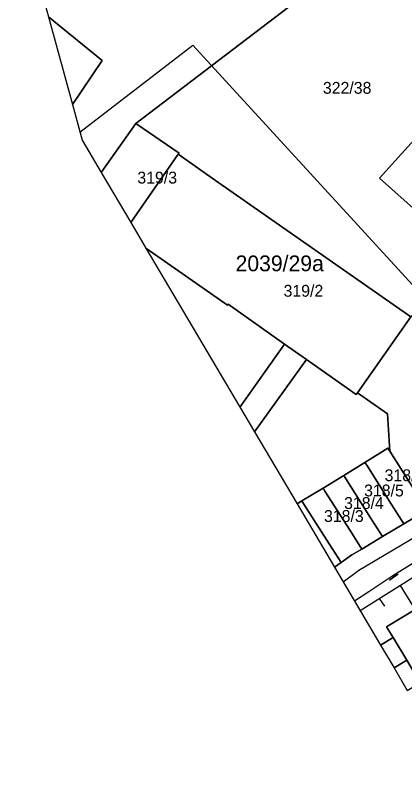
# Model space of a CAD drawing. Extents: x -571312 to -571060, y -1087128 to -1086933.
# Drawn here: x -571301.1 to -571251.9, y -1087104.3 to -1087007.2 of the extents above; entities that cross this region are included whole.
import ezdxf

# ---------------------------------------------------------------- set-up
doc = ezdxf.new("R2010")
doc.units = 0
for name, color, linetype in [('Adresní místo-text', 7, 'Continuous'), ('Armatura vodovodní', 7, 'Continuous'), ('Kanalizační přípojka', 7, 'Continuous'), ('Kanalizační stoka', 7, 'Continuous'), ('Parcela-polygon', 7, 'Continuous'), ('Parcela-text', 7, 'Continuous'), ('Vodovodní přípojka', 7, 'Continuous'), ('Vodovodní řad', 7, 'Continuous')]:
    doc.layers.add(name, color=color, linetype=linetype)

msp = doc.modelspace()

# ---------------------------------------------------------------- linework, layer by layer
at = {"layer": 'Armatura vodovodní'}
msp.add_lwpolyline([(-571252.784, -1087077.94), (-571253.789, -1087078.683), (-571253.836, -1087078.62), (-571252.831, -1087077.877), (-571252.784, -1087077.94)], dxfattribs=at)
at = {"layer": 'Kanalizační přípojka'}
for p in [(-571292.973, -1087021.985), (-571250, -1087042.322)]:
    msp.add_line(p, (-571278.716, -1087010.977), dxfattribs=at)
for points in [[(-571250.882, -1087081.901), (-571252.476, -1087079.36)], [(-571254.43, -1087081.96), (-571255.1, -1087081.01)]]:
    msp.add_lwpolyline(points, dxfattribs=at)
at = {"layer": 'Kanalizační stoka'}
msp.add_lwpolyline([(-571242.61, -1087073.17), (-571257.547, -1087082.542)], dxfattribs=at)
at = {"layer": 'Parcela-polygon'}
for p, q in [((-571301.139, -1086992.1), (-571296.961, -1087007.388)), ((-571296.961, -1087007.388), (-571293.935, -1087018.466)), ((-571290.277, -1087027.098), (-571286.558, -1087033.398)), ((-571286.558, -1087033.398), (-571284.641, -1087036.645)), ((-571284.641, -1087036.645), (-571272.809, -1087056.689)), ((-571272.809, -1087056.689), (-571270.904, -1087059.916)), ((-571270.904, -1087059.916), (-571265.528, -1087069.023)), ((-571265.528, -1087069.023), (-571260.789, -1087077.05)), ((-571260.789, -1087077.05), (-571254.973, -1087086.903)), ((-571254.973, -1087086.903), (-571253.275, -1087089.78)), ((-571253.275, -1087089.78), (-571251.598, -1087092.62))]:
    msp.add_line(p, q, dxfattribs=at)
for points in [[(-571290.277, -1087027.098), (-571285.9, -1087020.87), (-571258.67, -1087000.06), (-571254.9, -1086994.13), (-571254.35, -1086990.89), (-571259.84, -1086988.49), (-571269.65, -1086983.55), (-571272.76, -1086988.18), (-571271.26, -1086989.2), (-571273.59, -1086992.67), (-571275.1, -1086991.66), (-571277.9, -1086995.83), (-571276.89, -1086996.52), (-571278.45, -1086998.85), (-571279.47, -1086998.16), (-571283.95, -1087004.83), (-571292.34, -1086998.24), (-571293.32, -1086999.43), (-571295.27, -1086998.11), (-571294.32, -1086996.72), (-571301.139, -1086992.1)], [(-571296.961, -1087007.388), (-571290.18, -1087012.9), (-571293.935, -1087018.466)], [(-571293.935, -1087018.466), (-571290.18, -1087012.9), (-571296.961, -1087007.388)], [(-571152.8, -1087012.2), (-571165.57, -1087019.85), (-571178.15, -1087027.35), (-571184.85, -1087031.35), (-571187.38, -1087032.88), (-571199.42, -1087040.15), (-571212.04, -1087047.66), (-571212.62, -1087048.01), (-571217.5, -1087050.91), (-571220.52, -1087052.71), (-571223.27, -1087054.35), (-571244.48, -1087067.05), (-571249.13, -1087069.82), (-571252.04, -1087071.56), (-571254.73, -1087073.17), (-571257.35, -1087074.74), (-571258.59, -1087075.48), (-571259.95, -1087076.45), (-571260.789, -1087077.05)], [(-571293.935, -1087018.466), (-571292.695, -1087023.002), (-571290.277, -1087027.098)], [(-571286.558, -1087033.398), (-571280.58, -1087024.78), (-571280.44, -1087024.63), (-571285.9, -1087020.87), (-571290.277, -1087027.098)], [(-571254.973, -1087086.903), (-571253.39, -1087085.95), (-571254.21, -1087084.57), (-571245.94, -1087079.58), (-571237.74, -1087074.6), (-571228.73, -1087069.23), (-571219.73, -1087063.8), (-571210.82, -1087058.52), (-571201.86, -1087053.18), (-571190.56, -1087046.39), (-571189.72, -1087045.85), (-571184.97, -1087043.06), (-571183.51, -1087042.2), (-571177.42, -1087038.4), (-571168.35, -1087033.04), (-571159.39, -1087027.73), (-571150.57, -1087022.45)], [(-571284.641, -1087036.645), (-571282.71, -1087038), (-571274.33, -1087043.89), (-571274.24, -1087043.77), (-571267.11, -1087048.8), (-571264.33, -1087050.75), (-571258.05, -1087055.18), (-571257.9, -1087054.96), (-571251.17, -1087045.35), (-571275.83, -1087028.1), (-571280.58, -1087024.78), (-571286.558, -1087033.398)], [(-571272.809, -1087056.689), (-571272.71, -1087056.76), (-571267.11, -1087048.8), (-571274.24, -1087043.77), (-571274.33, -1087043.89), (-571282.71, -1087038), (-571284.641, -1087036.645)], [(-571270.904, -1087059.916), (-571264.33, -1087050.75), (-571267.11, -1087048.8), (-571272.71, -1087056.76), (-571272.809, -1087056.689)], [(-571265.528, -1087069.023), (-571264.92, -1087068.65), (-571262.25, -1087067.02), (-571259.64, -1087065.42), (-571256.95, -1087063.77), (-571254.05, -1087061.99), (-571253.82, -1087062.35), (-571254.11, -1087057.62), (-571257.9, -1087054.96), (-571258.05, -1087055.18), (-571264.33, -1087050.75), (-571270.904, -1087059.916)], [(-571260.789, -1087077.05), (-571259.95, -1087076.45), (-571261.47, -1087074.07), (-571264.67, -1087069.04), (-571264.92, -1087068.65), (-571265.528, -1087069.023)], [(-571253.275, -1087089.78), (-571251.65, -1087088.8), (-571253.39, -1087085.95), (-571254.973, -1087086.903)], [(-571251.598, -1087092.62), (-571250.99, -1087092.27), (-571249.96, -1087091.66), (-571251.65, -1087088.8), (-571253.275, -1087089.78)]]:
    msp.add_lwpolyline(points, dxfattribs=at)
for points in [[(-571280.58, -1087024.78), (-571275.83, -1087028.1), (-571251.17, -1087045.35), (-571243.07, -1087038.57), (-571255.12, -1087027.8), (-571244.8, -1087016.38), (-571238.33, -1087033.34), (-571236.49, -1087031.3), (-571239.35, -1087026.31), (-571252.89, -1086991.54), (-571254.35, -1086990.89), (-571254.9, -1086994.13), (-571258.67, -1087000.06), (-571285.9, -1087020.87), (-571280.44, -1087024.63)], [(-571243.07, -1087038.57), (-571238.33, -1087033.34), (-571244.8, -1087016.38), (-571255.12, -1087027.8)], [(-571244.48, -1087067.05), (-571223.27, -1087054.35), (-571236.49, -1087031.3), (-571238.33, -1087033.34), (-571243.07, -1087038.57), (-571251.17, -1087045.35), (-571257.9, -1087054.96), (-571254.11, -1087057.62), (-571253.82, -1087062.35), (-571250.71, -1087067.3), (-571249.13, -1087069.82)], [(-571252.04, -1087071.56), (-571249.13, -1087069.82), (-571250.71, -1087067.3), (-571253.82, -1087062.35), (-571254.05, -1087061.99), (-571256.95, -1087063.77), (-571256.72, -1087064.14), (-571253.59, -1087069.11)], [(-571256.95, -1087063.77), (-571259.64, -1087065.42), (-571259.4, -1087065.79), (-571256.24, -1087070.78), (-571254.73, -1087073.17), (-571252.04, -1087071.56), (-571253.59, -1087069.11), (-571256.72, -1087064.14)], [(-571259.64, -1087065.42), (-571262.25, -1087067.02), (-571262.01, -1087067.4), (-571258.83, -1087072.41), (-571257.35, -1087074.74), (-571254.73, -1087073.17), (-571256.24, -1087070.78), (-571259.4, -1087065.79)], [(-571262.01, -1087067.4), (-571262.25, -1087067.02), (-571264.92, -1087068.65), (-571264.67, -1087069.04), (-571261.47, -1087074.07), (-571259.95, -1087076.45), (-571258.59, -1087075.48), (-571257.35, -1087074.74), (-571258.83, -1087072.41)], [(-571254.21, -1087084.57), (-571253.39, -1087085.95), (-571251.65, -1087088.8), (-571249.96, -1087091.66), (-571249.14, -1087093.07), (-571242.3, -1087104.3), (-571239.74, -1087102.77), (-571239.52, -1087103.15), (-571239.41, -1087103.08), (-571243.72, -1087094.92), (-571238.58, -1087091.38), (-571240.73, -1087088.03), (-571242.19, -1087085.75), (-571245.94, -1087079.58)]]:
    msp.add_lwpolyline(points, close=True, dxfattribs=at)
at = {"layer": 'Vodovodní přípojka'}
msp.add_lwpolyline([(-571253.438, -1087078.107), (-571253.31, -1087078.28)], dxfattribs=at)
at = {"layer": 'Vodovodní řad'}
for points in [[(-571259.706, -1087078.885), (-571257.725, -1087077.417), (-571211.542, -1087050.048), (-571176.933, -1087029.184), (-571227.483, -1086941.667)], [(-571258.288, -1087081.288), (-571256.482, -1087080.103), (-571253.438, -1087078.107), (-571249.564, -1087075.668), (-571245.69, -1087073.23), (-571244.399, -1087072.489), (-571243.107, -1087071.749), (-571241.404, -1087071.94), (-571239.701, -1087072.13)]]:
    msp.add_lwpolyline(points, dxfattribs=at)

# ---------------------------------------------------------------- texts
at = {"layer": 'Adresní místo-text'}
msp.add_text('2039/29a', height=2, dxfattribs=at).set_placement((-571273.305, -1087039.59))
at = {"layer": 'Parcela-text'}
for s, p in [('322/38', (-571262.27, -1087017.13)), ('319/3', (-571285.72, -1087028.49)), ('319/2', (-571267.24, -1087042.81)), ('318/6', (-571254.47, -1087066.15)), ('318/5', (-571257.06, -1087068.08)), ('318/4', (-571259.59, -1087069.67)), ('318/3', (-571262.13, -1087071.31))]:
    msp.add_text(s, height=1.5, dxfattribs=at).set_placement(p)

doc.saveas('drawing.dxf')
